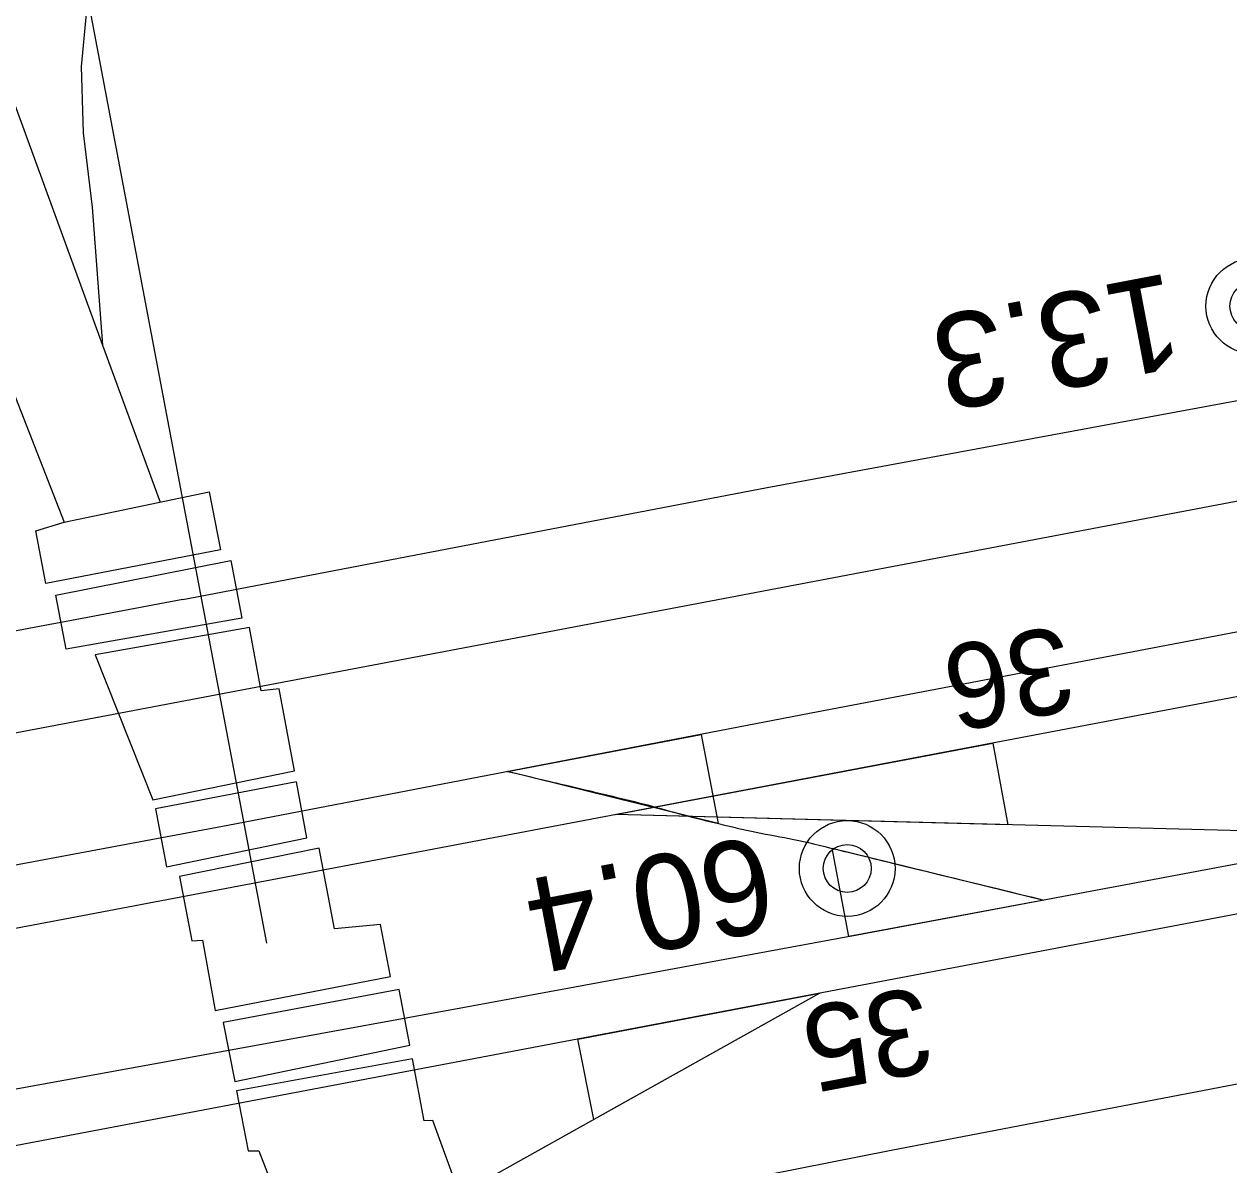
# Model space of a CAD drawing. Extents: x 6541740 to 6566395, y 5525066 to 5530361.
# Drawn here: x 6557453.65 to 6557479.06, y 5526209.06 to 5526233.1 of the extents above; entities that cross this region are included whole.
import ezdxf

# ---------------------------------------------------------------- set-up
doc = ezdxf.new("R2010")
doc.units = 0
for name, color, linetype in [('Domyślna', 7, 'Continuous'), ('TOR_PRZEK_P-komponent', 7, 'Continuous'), ('TOR_PS_OPIS_O-opisy odwodnienia', 7, 'Continuous'), ('TOR_PS_OPIS_T-opis geometrii-wzdluz_cz torowa', 7, 'Continuous'), ('TOR_PS_P-ogrodzenia', 7, 'Continuous'), ('TOR_PS_T-rowy otwarte nieumocnione', 7, 'Continuous'), ('TOR_PS_T-wypelnienia', 7, 'Continuous'), ('TOR_RAMKI-ramka+tabelka 1', 7, 'Continuous')]:
    doc.layers.add(name, color=color, linetype=linetype)

# ---------------------------------------------------------------- blocks, each defined once
blk = doc.blocks.new('4010_1')
at = {"layer": 'Domyślna'}
for radius in [0.75, 0.375]:
    blk.add_circle((0, 0), radius, dxfattribs=at)

msp = doc.modelspace()

# ---------------------------------------------------------------- linework, layer by layer
at = {"layer": 'TOR_PRZEK_P-komponent'}
for p, q in [((6557431.345, 5526213.97), (6557890.08, 5526300.925)), ((6557816.588, 5526278.292), (6557431.956, 5526205.384)), ((6557489.207, 5526220.816), (6557454.473, 5526214.232)), ((6557487.404, 5526215.894), (6557466.118, 5526216.439)), ((6557454.473, 5526214.232), (6557416.454, 5526207.025)), ((6557470.431, 5526212.677), (6557454.416, 5526203.738))]:
    msp.add_line(p, q, dxfattribs=at)
at = {"layer": 'TOR_PS_OPIS_T-opis geometrii-wzdluz_cz torowa'}
msp.add_line((6557458.768, 5526213.727), (6557448.235, 5526269.295), dxfattribs=at)
at = {"layer": 'TOR_PS_P-ogrodzenia'}
for p, q in [((6557466.118, 5526216.439), (6557474.078, 5526217.948)), ((6557465.323, 5526211.708), (6557470.431, 5526212.677))]:
    msp.add_line(p, q, dxfattribs=at)
for points in [[(6557474.078, 5526217.948), (6557474.392, 5526216.227), (6557466.118, 5526216.439)], [(6557470.431, 5526212.677), (6557465.662, 5526210.015), (6557465.323, 5526211.708)]]:
    msp.add_lwpolyline(points, dxfattribs=at)
at = {"layer": 'TOR_PS_T-rowy otwarte nieumocnione'}
for points in [[(6557548.233, 5526232.921), (6557507.053, 5526225.613), (6557502.954, 5526224.859), (6557500.224, 5526224.343), (6557494.768, 5526223.29), (6557494.768, 5526223.29), (6557482.503, 5526220.91), (6557482.503, 5526220.91), (6557470.214, 5526218.569), (6557470.214, 5526218.569), (6557457.942, 5526216.211), (6557457.941, 5526216.211), (6557445.676, 5526213.923), (6557445.676, 5526213.923), (6557433.375, 5526211.597), (6557433.375, 5526211.597), (6557421.103, 5526209.266)], [(6557548.233, 5526232.921), (6557507.053, 5526225.613), (6557502.954, 5526224.859), (6557500.224, 5526224.343), (6557494.768, 5526223.29), (6557494.768, 5526223.29), (6557482.503, 5526220.91), (6557482.503, 5526220.91), (6557470.214, 5526218.569), (6557470.214, 5526218.569), (6557457.942, 5526216.211), (6557457.941, 5526216.211), (6557445.676, 5526213.923), (6557445.676, 5526213.923), (6557433.375, 5526211.597), (6557433.375, 5526211.597), (6557421.103, 5526209.266)], [(6557549.068, 5526228.442), (6557507.95, 5526220.893), (6557507.949, 5526220.893), (6557503.851, 5526220.121), (6557495.664, 5526218.533), (6557495.664, 5526218.533), (6557487.481, 5526216.958), (6557482.022, 5526215.923), (6557471.101, 5526213.881), (6557471.1, 5526213.881), (6557462.933, 5526212.375), (6557458.848, 5526211.63), (6557458.848, 5526211.63), (6557450.61, 5526210.135), (6557446.494, 5526209.377), (6557442.394, 5526208.608), (6557434.2, 5526207.039), (6557434.2, 5526207.039), (6557421.947, 5526204.68)], [(6557549.068, 5526228.442), (6557507.95, 5526220.893), (6557507.949, 5526220.893), (6557503.851, 5526220.121), (6557495.664, 5526218.533), (6557495.664, 5526218.533), (6557487.481, 5526216.958), (6557482.022, 5526215.923), (6557471.101, 5526213.881), (6557471.1, 5526213.881), (6557462.933, 5526212.375), (6557458.848, 5526211.63), (6557458.848, 5526211.63), (6557450.61, 5526210.135), (6557446.494, 5526209.377), (6557442.394, 5526208.608), (6557434.2, 5526207.039), (6557434.2, 5526207.039), (6557421.947, 5526204.68)], [(6557456.992, 5526220.972), (6557469.32, 5526223.338), (6557481.593, 5526225.605)], [(6557456.992, 5526220.972), (6557469.32, 5526223.338), (6557481.593, 5526225.605)], [(6557456.991, 5526220.972), (6557454.981, 5526220.596), (6557454.423, 5526220.492), (6557445.07, 5526218.743)], [(6557456.991, 5526220.972), (6557454.981, 5526220.596), (6557454.423, 5526220.492), (6557445.07, 5526218.743)], [(6557459.776, 5526206.984), (6557463.245, 5526207.651), (6557463.582, 5526207.718), (6557471.937, 5526209.37), (6557484.261, 5526211.729)], [(6557459.776, 5526206.984), (6557463.245, 5526207.651), (6557463.582, 5526207.718), (6557471.937, 5526209.37), (6557484.261, 5526211.729)]]:
    msp.add_lwpolyline(points, dxfattribs=at)
for points in [[(6557463.841, 5526217.351), (6557467.924, 5526218.129), (6557468.283, 5526216.252)], [(6557463.841, 5526217.351), (6557467.924, 5526218.129), (6557468.283, 5526216.252)], [(6557475.155, 5526214.638), (6557471.04, 5526213.869), (6557470.687, 5526215.73)], [(6557475.155, 5526214.638), (6557471.04, 5526213.869), (6557470.687, 5526215.73)]]:
    msp.add_lwpolyline(points, close=True, dxfattribs=at)
msp.add_open_spline([(6557463.841, 5526217.351), (6557464.58, 5526217.176), (6557465.32, 5526217.001), (6557466.059, 5526216.826), (6557466.797, 5526216.651), (6557467.544, 5526216.43), (6557468.283, 5526216.252), (6557469.087, 5526216.059), (6557469.882, 5526215.927), (6557470.687, 5526215.73), (6557472.177, 5526215.366), (6557473.666, 5526215.002), (6557475.155, 5526214.638)], degree=3, dxfattribs=at)
msp.add_open_spline([(6557463.841, 5526217.351), (6557464.58, 5526217.176), (6557465.32, 5526217.001), (6557466.059, 5526216.826), (6557466.797, 5526216.651), (6557467.544, 5526216.43), (6557468.283, 5526216.252), (6557469.087, 5526216.059), (6557469.882, 5526215.927), (6557470.687, 5526215.73), (6557472.177, 5526215.366), (6557473.666, 5526215.002), (6557475.155, 5526214.638)], degree=3, dxfattribs=at)
msp.add_open_spline([(6557463.841, 5526217.351), (6557464.58, 5526217.176), (6557465.32, 5526217.001), (6557466.059, 5526216.826), (6557466.797, 5526216.651), (6557467.544, 5526216.43), (6557468.283, 5526216.252), (6557469.087, 5526216.059), (6557469.882, 5526215.927), (6557470.687, 5526215.73), (6557472.177, 5526215.366), (6557473.666, 5526215.002), (6557475.155, 5526214.638)], degree=3, dxfattribs=at)
msp.add_open_spline([(6557463.841, 5526217.351), (6557464.58, 5526217.176), (6557465.32, 5526217.001), (6557466.059, 5526216.826), (6557466.797, 5526216.651), (6557467.544, 5526216.43), (6557468.283, 5526216.252), (6557469.087, 5526216.059), (6557469.882, 5526215.927), (6557470.687, 5526215.73), (6557472.177, 5526215.366), (6557473.666, 5526215.002), (6557475.155, 5526214.638)], degree=3, dxfattribs=at)
at = {"layer": 'TOR_PS_T-wypelnienia'}
msp.add_line((6557455.079, 5526229.243), (6557455.303, 5526226.338), dxfattribs=at)
msp.add_line((6557455.079, 5526229.243), (6557455.303, 5526226.338), dxfattribs=at)
for points in [[(6557442.212, 5526260.429), (6557449.478, 5526241.774), (6557451.029, 5526238.034), (6557455.303, 5526226.338), (6557456.514, 5526223.026)], [(6557442.212, 5526260.429), (6557449.478, 5526241.774), (6557451.029, 5526238.034), (6557455.303, 5526226.338), (6557456.514, 5526223.026)], [(6557441.271, 5526255.657), (6557442.044, 5526253.677), (6557443.159, 5526250.82), (6557445.03, 5526246.221), (6557448.898, 5526236.712), (6557449.632, 5526234.883), (6557451.494, 5526230.242), (6557451.808, 5526229.462), (6557454.493, 5526222.601)], [(6557441.271, 5526255.657), (6557442.044, 5526253.677), (6557443.159, 5526250.82), (6557445.03, 5526246.221), (6557448.898, 5526236.712), (6557449.632, 5526234.883), (6557451.494, 5526230.242), (6557451.808, 5526229.462), (6557454.493, 5526222.601)], [(6557455.194, 5526234.062), (6557454.954, 5526233.322), (6557454.85, 5526232.207), (6557454.893, 5526230.808), (6557455.079, 5526229.243)], [(6557455.194, 5526234.062), (6557454.954, 5526233.322), (6557454.85, 5526232.207), (6557454.893, 5526230.808), (6557455.079, 5526229.243)]]:
    msp.add_lwpolyline(points, dxfattribs=at)
for points in [[(6557457.551, 5526223.244), (6557457.786, 5526222.023), (6557454.106, 5526221.31), (6557453.895, 5526222.425), (6557454.493, 5526222.601)], [(6557457.551, 5526223.244), (6557457.786, 5526222.023), (6557454.106, 5526221.31), (6557453.895, 5526222.425), (6557454.493, 5526222.601)], [(6557454.314, 5526221.066), (6557458.01, 5526221.799), (6557458.238, 5526220.579), (6557454.531, 5526219.925)], [(6557454.314, 5526221.066), (6557458.01, 5526221.799), (6557458.238, 5526220.579), (6557454.531, 5526219.925)], [(6557458.401, 5526220.384), (6557455.147, 5526219.811), (6557456.364, 5526216.753), (6557459.347, 5526217.364), (6557459.028, 5526219.09), (6557458.647, 5526219.048)], [(6557458.401, 5526220.384), (6557455.147, 5526219.811), (6557456.364, 5526216.753), (6557459.347, 5526217.364), (6557459.028, 5526219.09), (6557458.647, 5526219.048)], [(6557459.39, 5526217.131), (6557456.419, 5526216.563), (6557456.648, 5526215.339), (6557459.608, 5526215.951)], [(6557459.39, 5526217.131), (6557456.419, 5526216.563), (6557456.648, 5526215.339), (6557459.608, 5526215.951)], [(6557459.869, 5526215.731), (6557456.925, 5526215.139), (6557457.186, 5526213.78), (6557457.407, 5526213.791), (6557457.677, 5526212.31), (6557461.377, 5526213.029), (6557461.163, 5526214.122), (6557460.191, 5526214.029)], [(6557459.869, 5526215.731), (6557456.925, 5526215.139), (6557457.186, 5526213.78), (6557457.407, 5526213.791), (6557457.677, 5526212.31), (6557461.377, 5526213.029), (6557461.163, 5526214.122), (6557460.191, 5526214.029)], [(6557461.558, 5526212.752), (6557457.848, 5526212.059), (6557458.091, 5526210.813), (6557461.78, 5526211.581)], [(6557461.558, 5526212.752), (6557457.848, 5526212.059), (6557458.091, 5526210.813), (6557461.78, 5526211.581)], [(6557461.835, 5526211.29), (6557458.129, 5526210.615), (6557458.375, 5526209.355), (6557458.595, 5526209.351), (6557459.23, 5526207.722), (6557462.852, 5526208.394), (6557462.27, 5526209.989), (6557462.083, 5526209.984)], [(6557461.835, 5526211.29), (6557458.129, 5526210.615), (6557458.375, 5526209.355), (6557458.595, 5526209.351), (6557459.23, 5526207.722), (6557462.852, 5526208.394), (6557462.27, 5526209.989), (6557462.083, 5526209.984)]]:
    msp.add_lwpolyline(points, close=True, dxfattribs=at)

# ---------------------------------------------------------------- block references
at = {"layer": 'TOR_RAMKI-ramka+tabelka 1', "xscale": 1.345963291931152, "yscale": 1.345963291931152}
for p in [(6557479.583, 5526227.158), (6557471.007, 5526215.305)]:
    msp.add_blockref('4010_1', p, dxfattribs=at)

# ---------------------------------------------------------------- texts
at = {"layer": 'TOR_PS_OPIS_O-opisy odwodnienia'}
for s, p in [('36', (6557475.567, 5526220.442)), ('35', (6557472.589, 5526212.832))]:
    msp.add_text(s, height=1.8, rotation=190.7332, dxfattribs=at).set_placement(p)
at = {"layer": 'TOR_RAMKI-ramka+tabelka 1'}
for s, p in [('13.3', (6557477.809, 5526227.865)), ('60.4', (6557469.228, 5526216.012))]:
    msp.add_text(s, height=2, rotation=190.7691, dxfattribs=at).set_placement(p)

doc.saveas('drawing.dxf')
